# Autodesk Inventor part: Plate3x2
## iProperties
Created: 2006-02
Part Number: Plate3x2
Material: Stainless Steel
Document SubType Name: Modeling
Designer: 40664
Mass: 200889 g
Surface Area: 50370 cm^2
Volume: 24862.5 cm^3
Density: 8.08 g/cm^3
CSToolsMass: 201.0
CSToolsVolume: 24862500.0
CSToolsArea: 50370.0
Author: 40664
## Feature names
1. Extrusion2
